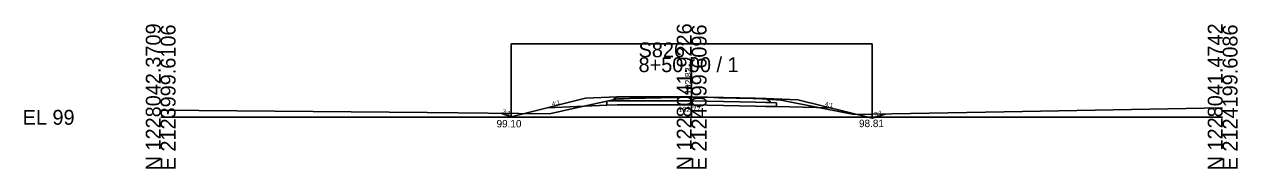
# Model space of a CAD drawing. Extents: x 2118382 to 2118616, y 1213030 to 1222057.
# Drawn here: x 2118381.9 to 2118610.4, y 1219030.1 to 1219057.3 of the extents above; entities that cross this region are included whole.
import ezdxf

# ---------------------------------------------------------------- set-up
doc = ezdxf.new("R2010")
doc.units = 0
for name, color, linetype in [('XS_CELL', 7, 'Continuous'), ('XS_M_DITCH', 7, 'Continuous'), ('XS_P_FINISHED_GRADE', 7, 'Continuous'), ('XS_P_FINISHED_GRADE_ELEV_TX', 7, 'Continuous'), ('XS_P_SUBGRADE_GRANULAR', 7, 'Continuous'), ('XS_P_SUBGRADE_PAVEMENT', 7, 'Continuous'), ('XS_P_TX_DCH', 7, 'Continuous'), ('XS_P_TX_FS_BS', 7, 'Continuous'), ('XS_X_GROUND', 7, 'Continuous'), ('XS_X_GROUND_TX', 7, 'Continuous')]:
    doc.layers.add(name, color=color, linetype=linetype)

msp = doc.modelspace()

# ---------------------------------------------------------------- linework, layer by layer
at = {"layer": 'XS_CELL'}
for p, q in [((2118507.6, 1219039.8), (2118507.6, 1219051.11)), ((2118407.6, 1219039.8), (2118507.6, 1219039.8)), ((2118507.6, 1219039.8), (2118607.6, 1219039.8))]:
    msp.add_line(p, q, dxfattribs=at)
at = {"layer": 'XS_M_DITCH'}
for p, q in [((2118473.6, 1219039.9), (2118473.6, 1219053.63)), ((2118473.6, 1219053.63), (2118541.6, 1219053.63)), ((2118541.6, 1219053.63), (2118541.6, 1219039.61))]:
    msp.add_line(p, q, dxfattribs=at)
at = {"layer": 'XS_P_FINISHED_GRADE'}
for p, q in [((2118487.6, 1219043.4), (2118473.6, 1219039.9)), ((2118493.6, 1219043.64), (2118487.6, 1219043.4)), ((2118495.6, 1219043.64), (2118493.6, 1219043.64)), ((2118495.6, 1219043.64), (2118507.6, 1219043.63)), ((2118507.6, 1219043.63), (2118519.6, 1219043.39)), ((2118519.6, 1219043.39), (2118521.6, 1219043.35)), ((2118521.6, 1219043.35), (2118527.6, 1219043.11)), ((2118527.6, 1219043.11), (2118541.6, 1219039.61)), ((2118473.6, 1219039.9), (2118471.65, 1219040.55)), ((2118541.6, 1219039.61), (2118544.03, 1219040.42))]:
    msp.add_line(p, q, dxfattribs=at)
at = {"layer": 'XS_P_SUBGRADE_GRANULAR'}
for p, q in [((2118491.6, 1219042.06), (2118480.46, 1219041.61)), ((2118492.74, 1219042.89), (2118491.6, 1219042.85)), ((2118491.6, 1219042.06), (2118491.6, 1219042.85)), ((2118493.6, 1219042.14), (2118491.6, 1219042.06)), ((2118495.6, 1219042.14), (2118493.6, 1219042.14)), ((2118495.6, 1219042.14), (2118507.6, 1219042.13)), ((2118507.6, 1219042.13), (2118519.6, 1219041.89)), ((2118519.6, 1219041.89), (2118521.6, 1219041.85)), ((2118521.6, 1219041.85), (2118523.6, 1219041.81)), ((2118521.6, 1219041.85), (2118523.6, 1219041.81)), ((2118522.46, 1219042.57), (2118523.6, 1219042.52)), ((2118523.6, 1219041.81), (2118523.6, 1219042.52)), ((2118523.6, 1219041.81), (2118533.6, 1219041.61))]:
    msp.add_line(p, q, dxfattribs=at)
at = {"layer": 'XS_P_SUBGRADE_PAVEMENT'}
for p, q in [((2118492.91, 1219043.18), (2118492.74, 1219042.89)), ((2118493.6, 1219043.64), (2118492.91, 1219043.18)), ((2118521.6, 1219043.35), (2118522.28, 1219042.88)), ((2118495.6, 1219042.89), (2118492.74, 1219042.89)), ((2118495.6, 1219042.89), (2118507.6, 1219042.88)), ((2118507.6, 1219042.88), (2118519.6, 1219042.64)), ((2118519.6, 1219042.64), (2118521.6, 1219042.6)), ((2118521.6, 1219042.6), (2118522.46, 1219042.57)), ((2118522.28, 1219042.88), (2118522.46, 1219042.57))]:
    msp.add_line(p, q, dxfattribs=at)
at = {"layer": 'XS_X_GROUND'}
for p, q in [((2118485.83, 1219041.6), (2118493.69, 1219043.3)), ((2118493.69, 1219043.3), (2118494.86, 1219043.3)), ((2118494.86, 1219043.3), (2118495.93, 1219043.34)), ((2118495.93, 1219043.34), (2118504.82, 1219043.51)), ((2118504.82, 1219043.51), (2118507.6, 1219043.57)), ((2118507.6, 1219043.57), (2118507.6, 1219043.57)), ((2118507.6, 1219043.57), (2118511.8, 1219043.5)), ((2118511.8, 1219043.5), (2118512.81, 1219043.48)), ((2118512.81, 1219043.48), (2118519.09, 1219043.37)), ((2118519.09, 1219043.37), (2118519.94, 1219043.33)), ((2118519.94, 1219043.33), (2118524.46, 1219043.05)), ((2118407.6, 1219041.14), (2118457.78, 1219040.68)), ((2118480.85, 1219040.46), (2118485.83, 1219041.6)), ((2118524.46, 1219043.05), (2118526.63, 1219042.61)), ((2118526.63, 1219042.61), (2118538.22, 1219040.32)), ((2118566.43, 1219040.8), (2118607.6, 1219041.6)), ((2118457.78, 1219040.68), (2118480.85, 1219040.46)), ((2118538.22, 1219040.32), (2118566.43, 1219040.8))]:
    msp.add_line(p, q, dxfattribs=at)

# ---------------------------------------------------------------- texts
at = {"layer": 'XS_CELL'}
for s, p in [('N 1228042.3709', (2118407.6, 1219029.8)), ('E 2123999.6106', (2118410.4, 1219029.8)), ('N 1228041.9226', (2118507.6, 1219029.8)), ('E 2124099.6096', (2118510.4, 1219029.8)), ('N 1228041.4742', (2118607.6, 1219029.8)), ('E 2124199.6086', (2118610.4, 1219029.8))]:
    msp.add_text(s, height=2.8, rotation=90, dxfattribs=at).set_placement(p)
for s, p in [('S826', (2118497.6, 1219051.11)), ('8+50.00 / 1', (2118497.6, 1219048.31)), ('EL 99', (2118381.6, 1219038.4))]:
    msp.add_text(s, height=2.8, dxfattribs=at).set_placement(p)
at = {"layer": 'XS_P_FINISHED_GRADE_ELEV_TX'}
msp.add_text(' 102.83', height=1.25, rotation=90, dxfattribs=at).set_placement((2118507.6, 1219043.63))
at = {"layer": 'XS_P_TX_DCH'}
for s, p in [('99.10', (2118470.86, 1219037.9)), ('98.81', (2118539.12, 1219037.95))]:
    msp.add_text(s, height=1.4, dxfattribs=at).set_placement(p)
at = {"layer": 'XS_P_TX_FS_BS'}
for s, rotation, p in [('3:1', 341.5651, (2118471.9, 1219040.64)), ('4:1', 14.0362, (2118481.39, 1219041.94)), ('4:1', 345.9638, (2118532.65, 1219041.99)), ('3:1', 18.4349, (2118542.14, 1219039.9))]:
    msp.add_text(s, height=0.8, rotation=rotation, dxfattribs=at).set_placement(p)
at = {"layer": 'XS_X_GROUND_TX'}
msp.add_text('102.77', height=1, dxfattribs=at).set_placement((2118505.05, 1219040.78))

doc.saveas('drawing.dxf')
